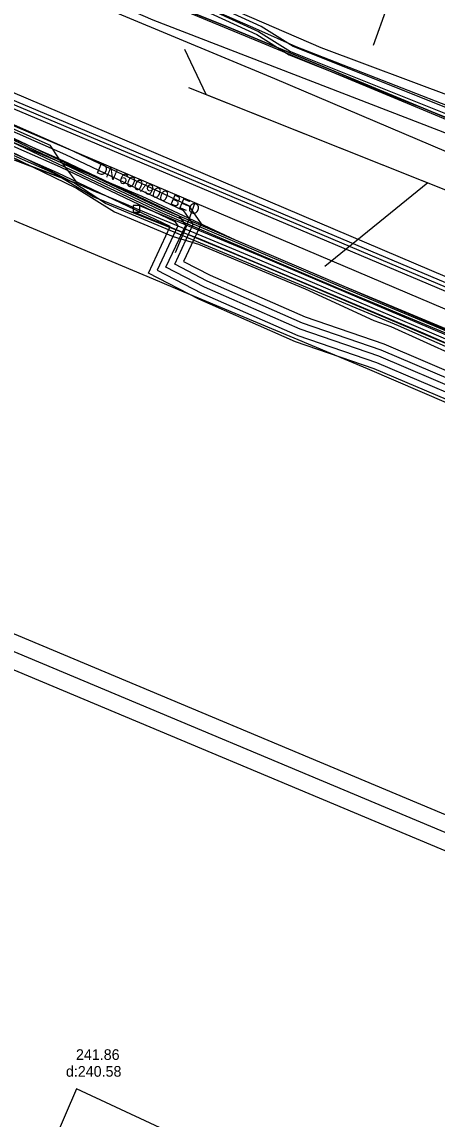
# Model space of a CAD drawing. Extents: x -596024 to -594475, y -1163820 to -1161957.
# Drawn here: x -594762.9 to -594731.8, y -1162272.9 to -1162190.6 of the extents above; entities that cross this region are included whole.
import ezdxf

# ---------------------------------------------------------------- set-up
doc = ezdxf.new("R2010")
doc.units = 0
for name, color, linetype in [('Level 1', 7, 'Continuous'), ('Vrstva 1', 7, 'Continuous'), ('Vrstva 10', 7, 'Continuous'), ('Vrstva 11', 7, 'Continuous'), ('Vrstva 12', 7, 'Continuous'), ('Vrstva 13', 7, 'Continuous'), ('Vrstva 19', 7, 'Continuous'), ('Vrstva 29', 7, 'Continuous'), ('Vrstva 30', 7, 'Continuous'), ('Vrstva 4', 7, 'Continuous'), ('Vrstva 42', 7, 'Continuous'), ('Vrstva 44', 7, 'Continuous'), ('Vrstva 55', 7, 'Continuous'), ('Vrstva 58', 7, 'Continuous'), ('Vrstva 9', 7, 'Continuous')]:
    doc.layers.add(name, color=color, linetype=linetype)

msp = doc.modelspace()

# ---------------------------------------------------------------- linework, layer by layer
at = {"layer": 'Level 1'}
for points in [[(-594749.13, -1162196.07), (-594750.72, -1162192.68)], [(-594750.45, -1162195.55), (-594709.77, -1162211.75), (-594681.66, -1162222.95), (-594639.16, -1162241.84), (-594604.2, -1162257.38), (-594561.16, -1162275.84)], [(-594732.5, -1162202.7), (-594740.23, -1162208.96)]]:
    msp.add_lwpolyline(points, dxfattribs=at)
at = {"layer": 'Vrstva 1'}
for p, q in [((-594758.849, -1162270.671), (-594770.885, -1162298.534)), ((-594744.151, -1162277.481), (-594758.849, -1162270.671))]:
    msp.add_line(p, q, dxfattribs=at)
msp.add_lwpolyline([(-594750.45, -1162195.55), (-594749.13, -1162196.07), (-594732.5, -1162202.7), (-594723.2, -1162206.4), (-594709.77, -1162211.75)], dxfattribs=at)
at = {"layer": 'Vrstva 10'}
for points in [[(-594776.154, -1162191.153), (-594772.298, -1162192.772), (-594764.852, -1162195.956), (-594763.349, -1162196.593), (-594741.779, -1162205.699), (-594725.074, -1162212.755), (-594718.123, -1162215.684)], [(-594718.357, -1162216.236), (-594725.307, -1162213.307), (-594742.013, -1162206.252), (-594763.583, -1162197.146), (-594765.087, -1162196.508), (-594772.532, -1162193.325), (-594776.386, -1162191.707)], [(-594708.531, -1162223.765), (-594716.132, -1162220.484), (-594733.443, -1162213.114), (-594744.984, -1162208.224), (-594754.234, -1162204.353)], [(-594708.769, -1162224.315), (-594716.368, -1162221.036), (-594733.677, -1162213.666), (-594745.216, -1162208.776), (-594754.466, -1162204.907)]]:
    msp.add_lwpolyline(points, dxfattribs=at)
at = {"layer": 'Vrstva 11'}
msp.add_lwpolyline([(-594754.6, -1162204.88), (-594754.1, -1162204.88), (-594754.1, -1162204.38), (-594754.6, -1162204.38)], close=True, dxfattribs=at)
msp.add_lwpolyline([(-594754.6, -1162204.88), (-594754.1, -1162204.88), (-594754.1, -1162204.38), (-594754.6, -1162204.38)], close=True, dxfattribs=at)
at = {"layer": 'Vrstva 12'}
msp.add_line((-594758.77, -1162202.76), (-594763.45, -1162200.98), dxfattribs=at)
for points in [[(-594691.9, -1162214.74), (-594693.41, -1162214.13), (-594708.66, -1162207.82), (-594726.57, -1162199.83), (-594745.03, -1162192.17), (-594754.89, -1162188.06), (-594753.69, -1162185.32)], [(-594797.84, -1162197.92), (-594795.26, -1162191.95), (-594785.4, -1162196.2), (-594782.44, -1162197.47), (-594767.54, -1162203.83), (-594753.11, -1162209.88)], [(-594767.38, -1162194.31), (-594722.65, -1162213.34), (-594687.5, -1162228.11)], [(-594767.74, -1162196.85), (-594765.07, -1162197.98), (-594760.82, -1162199.87)], [(-594766.88, -1162199.71), (-594758.77, -1162202.76)], [(-594758.77, -1162202.76), (-594758.93, -1162202.52), (-594760.19, -1162200.82), (-594760.82, -1162199.87)], [(-594669.22, -1162240.87), (-594677.04, -1162237.37), (-594688.06, -1162232.7), (-594698.57, -1162228.36), (-594704, -1162226.27), (-594707.98, -1162224.37), (-594708.65, -1162224.04), (-594716.25, -1162220.76), (-594733.56, -1162213.39), (-594745.1, -1162208.5), (-594754.35, -1162204.63), (-594755.28, -1162204.24), (-594755.87, -1162204), (-594756.43, -1162203.77), (-594756.78, -1162203.62), (-594757.22, -1162203.43), (-594757.54, -1162203.32), (-594758.33, -1162202.96), (-594758.77, -1162202.76), (-594758.93, -1162202.52), (-594760.19, -1162200.82), (-594760.82, -1162199.87)], [(-594758.33, -1162202.96), (-594758.77, -1162202.76)], [(-594758.33, -1162202.96), (-594758.77, -1162202.76)], [(-594757.54, -1162203.32), (-594758.33, -1162202.96)], [(-594757.54, -1162203.32), (-594758.33, -1162202.96)], [(-594757.22, -1162203.43), (-594757.54, -1162203.32)], [(-594757.22, -1162203.43), (-594757.54, -1162203.32)], [(-594756.78, -1162203.62), (-594757.22, -1162203.43)], [(-594756.78, -1162203.62), (-594757.22, -1162203.43)], [(-594756.43, -1162203.77), (-594756.78, -1162203.62)], [(-594756.43, -1162203.77), (-594756.78, -1162203.62)], [(-594755.87, -1162204), (-594756.43, -1162203.77)], [(-594755.87, -1162204), (-594756.43, -1162203.77)], [(-594755.28, -1162204.24), (-594755.87, -1162204)], [(-594755.28, -1162204.24), (-594755.87, -1162204)], [(-594754.35, -1162204.63), (-594755.28, -1162204.24)], [(-594753.11, -1162209.88), (-594750.79, -1162210.86)], [(-594750.79, -1162210.86), (-594737.05, -1162216.62), (-594699.17, -1162232.93)]]:
    msp.add_lwpolyline(points, dxfattribs=at)
at = {"layer": 'Vrstva 13'}
msp.add_lwpolyline([(-594836.23, -1162155.443), (-594836.196, -1162155.782), (-594816.247, -1162164.384), (-594814.935, -1162164.957), (-594803.879, -1162169.64), (-594755.473, -1162190.086), (-594744.01, -1162194.87), (-594731.121, -1162200.339), (-594730.015, -1162200.811), (-594704.47, -1162211.75), (-594699.45, -1162213.94), (-594673.314, -1162225.133)], dxfattribs=at)
at = {"layer": 'Vrstva 19'}
for points in [[(-594695.25, -1162276.17), (-594690.21, -1162265.28), (-594680.2, -1162243.33), (-594679.351, -1162240.241), (-594678.82, -1162238.33), (-594678.078, -1162235.421), (-594674.9, -1162222.97), (-594673.86, -1162218.9), (-594682.15, -1162216.27), (-594693.73, -1162211.66), (-594707.83, -1162205.54), (-594713.34, -1162203.16), (-594714.6, -1162202.61), (-594730.47, -1162196.31), (-594740.5, -1162192.55), (-594751.07, -1162187.95), (-594753.63, -1162189.06), (-594775.09, -1162179.85), (-594776.07, -1162176.84), (-594793.1, -1162168.81), (-594802.09, -1162164.76), (-594816.08, -1162158.49), (-594834.13, -1162150.42), (-594853.67, -1162141.96)], [(-594685.55, -1162231.56), (-594692.94, -1162228.45), (-594699.49, -1162225.65), (-594749.98, -1162204.19), (-594785.76, -1162188.98), (-594797.35, -1162184.05)], [(-594749.98, -1162204.19), (-594750.56, -1162205.79), (-594751.45, -1162207.94)]]:
    msp.add_lwpolyline(points, dxfattribs=at)
at = {"layer": 'Vrstva 29'}
msp.add_line((-594727.603, -1162252.954), (-594776.519, -1162232.441), dxfattribs=at)
at = {"layer": 'Vrstva 30'}
for p, q in [((-594776.036, -1162231.288), (-594727.903, -1162251.472)), ((-594727.302, -1162254.435), (-594777.002, -1162233.594))]:
    msp.add_line(p, q, dxfattribs=at)
at = {"layer": 'Vrstva 42'}
for points in [[(-594841.22, -1162164.89), (-594841.55, -1162165.818), (-594823.941, -1162173.342), (-594805.527, -1162181.255), (-594786.096, -1162189.732), (-594763.998, -1162199.133), (-594752.438, -1162204.617), (-594739.102, -1162210.309), (-594723.16, -1162216.972), (-594709.798, -1162222.556), (-594699.416, -1162226.808), (-594686.936, -1162232.243), (-594670.535, -1162239.442), (-594642.912, -1162251.21), (-594626.307, -1162258.207), (-594595.818, -1162271.123), (-594582.146, -1162276.922), (-594568.678, -1162282.65), (-594548.298, -1162291.531), (-594530.464, -1162298.451), (-594511.972, -1162306.232), (-594493.611, -1162313.902), (-594475.47, -1162321.871)], [(-594805, -1162180.3), (-594805.561, -1162181.567), (-594805.473, -1162181.605), (-594786.214, -1162190.008), (-594764.122, -1162199.407), (-594752.562, -1162204.891), (-594739.218, -1162210.585), (-594723.276, -1162217.248), (-594709.912, -1162222.834), (-594699.532, -1162227.084), (-594687.056, -1162232.517), (-594670.655, -1162239.718), (-594643.03, -1162251.486), (-594626.423, -1162258.483), (-594595.936, -1162271.399), (-594582.264, -1162277.198), (-594568.796, -1162282.926), (-594548.412, -1162291.809), (-594530.576, -1162298.729), (-594512.088, -1162306.508), (-594493.729, -1162314.178), (-594475.47, -1162322.199)], [(-594475.47, -1162322.035), (-594492.486, -1162314.56), (-594509.999, -1162307.221), (-594528.715, -1162299.349), (-594548.355, -1162291.67), (-594568.737, -1162282.788), (-594582.205, -1162277.06), (-594595.877, -1162271.261), (-594626.365, -1162258.345), (-594642.971, -1162251.348), (-594670.595, -1162239.58), (-594686.996, -1162232.38), (-594699.474, -1162226.946), (-594709.855, -1162222.695), (-594723.218, -1162217.11), (-594739.16, -1162210.447), (-594752.5, -1162204.754), (-594764.06, -1162199.27), (-594786.155, -1162189.87), (-594805.5, -1162181.43)], [(-594615.74, -1162262.79), (-594624.65, -1162259.07), (-594637.95, -1162253.48), (-594653.13, -1162246.96), (-594666.17, -1162241.28), (-594679.92, -1162235.52), (-594687.43, -1162232.45), (-594694.39, -1162229.4), (-594701, -1162226.48), (-594711.77, -1162221.9), (-594718.09, -1162219.27), (-594728.65, -1162214.76), (-594737.08, -1162211.18), (-594746.93, -1162206.99), (-594753.92, -1162203.71), (-594761.99, -1162200.35), (-594768.71, -1162197.49), (-594777.63, -1162193.65), (-594785.3, -1162190.25), (-594792.89, -1162187), (-594796.23, -1162185.84), (-594796.51, -1162185.77), (-594796.81, -1162185.85)], [(-594719.13, -1162220.27), (-594734.71, -1162213.43), (-594756.68, -1162204.25), (-594759.04, -1162202.69), (-594761.37, -1162201.52), (-594767.166, -1162198.707), (-594767.895, -1162200.415), (-594768.078, -1162200.336), (-594768.262, -1162200.258), (-594767.529, -1162198.541), (-594769.39, -1162198.13), (-594789.46, -1162189.22), (-594796.506, -1162186.659), (-594797.09, -1162187.201), (-594800.802, -1162195.021)], [(-594763.837, -1162200.659), (-594758.837, -1162203.099), (-594756.007, -1162204.859), (-594751.587, -1162206.709), (-594749.697, -1162207.299), (-594741.697, -1162210.639), (-594736.547, -1162213.009), (-594735.267, -1162213.479), (-594730.417, -1162215.679), (-594720.697, -1162219.769), (-594715.217, -1162222.125), (-594714.778, -1162222.42), (-594713.279, -1162223.092), (-594712.844, -1162222.824), (-594712.197, -1162221.469), (-594707.027, -1162209.629), (-594703.467, -1162201.819)]]:
    msp.add_lwpolyline(points, dxfattribs=at)
at = {"layer": 'Vrstva 44'}
msp.add_lwpolyline([(-594615.489, -1162264.329), (-594617.876, -1162263.185), (-594624.753, -1162260.392), (-594653.042, -1162248.004), (-594673.87, -1162239.439), (-594676.32, -1162238.996), (-594700.937, -1162228.271), (-594701.517, -1162227.634), (-594706.4, -1162225.55), (-594708.626, -1162224.544), (-594732.851, -1162213.96), (-594749.58, -1162206.904), (-594751.558, -1162206.159), (-594757.592, -1162203.739), (-594760.561, -1162201.965), (-594774.949, -1162195.637), (-594776.33, -1162195.028), (-594780.641, -1162193.061), (-594785.301, -1162190.858), (-594797.218, -1162185.869), (-594798.27, -1162185.406), (-594820.513, -1162176.019), (-594846.169, -1162165.001), (-594853.363, -1162161.962)], dxfattribs=at)
at = {"layer": 'Vrstva 55'}
for points in [[(-594752.53, -1162187.98), (-594745.42, -1162191.12), (-594742.39, -1162192.46), (-594730.47, -1162197.12)], [(-594729.61, -1162217.96), (-594735.99, -1162215.24), (-594741.89, -1162213.21), (-594749.04, -1162210.06), (-594751.48, -1162208.8), (-594750.09, -1162205.8), (-594750.8, -1162204.79), (-594759.66, -1162200.58), (-594768.61, -1162196.65)], [(-594767.62, -1162196.54), (-594759.45, -1162200.13), (-594750.46, -1162204.39), (-594749.51, -1162205.76), (-594750.82, -1162208.58), (-594748.82, -1162209.61), (-594741.71, -1162212.75), (-594735.81, -1162214.77), (-594729.42, -1162217.5)], [(-594729.84, -1162218.4), (-594736.17, -1162215.7), (-594742.08, -1162213.68), (-594749.25, -1162210.51), (-594752.14, -1162209.02), (-594750.66, -1162205.86), (-594751.13, -1162205.18), (-594759.86, -1162201.04), (-594768.44, -1162197.27)], [(-594768.26, -1162197.9), (-594760.07, -1162201.49), (-594751.47, -1162205.58), (-594751.24, -1162205.91), (-594752.79, -1162209.25), (-594749.47, -1162210.96), (-594742.26, -1162214.15), (-594736.35, -1162216.17), (-594730, -1162218.88)], [(-594671.35, -1162238.82), (-594675.31, -1162238.9), (-594677.31, -1162239.54), (-594677.53, -1162240.35), (-594678.35, -1162242.07), (-594679.96, -1162243.68), (-594683.01, -1162244.53), (-594696.54, -1162238.61), (-594696.59, -1162236.5), (-594698.58, -1162232.15), (-594700.76, -1162231.89), (-594709.45, -1162229.42), (-594721.25, -1162223.49), (-594722.48, -1162222.58), (-594724.08, -1162222.23), (-594730.27, -1162219.3), (-594736.53, -1162216.64), (-594742.43, -1162214.61), (-594749.68, -1162211.41), (-594753.45, -1162209.47), (-594751.82, -1162205.97), (-594760.28, -1162201.95), (-594768.08, -1162198.52)]]:
    msp.add_lwpolyline(points, dxfattribs=at)
at = {"layer": 'Vrstva 58'}
for points in [[(-594855.8, -1162145.62), (-594837.62, -1162153.37), (-594836.31, -1162153.98), (-594819.51, -1162161.12), (-594801.35, -1162168.87), (-594799.77, -1162169.48), (-594797.27, -1162170.37), (-594784.28, -1162175.73), (-594782.11, -1162176.71), (-594778.76, -1162179.27), (-594754.53, -1162189.16), (-594752.65, -1162189.31), (-594750.57, -1162189.75), (-594747.53, -1162190.99), (-594651.85, -1162230.77), (-594634.34, -1162238.31), (-594628.08, -1162237.31), (-594627.27, -1162237.69), (-594626.17, -1162238.17), (-594617.89, -1162242.16), (-594607.87, -1162246.62)], [(-594855.521, -1162146.975), (-594837.445, -1162154.525), (-594819.368, -1162162.393), (-594800.867, -1162170.155), (-594782.472, -1162177.705), (-594753.124, -1162190.465), (-594723.671, -1162201.842), (-594694.961, -1162212.9), (-594661.467, -1162226.404), (-594631.163, -1162239.589), (-594604.155, -1162251.18), (-594572.468, -1162264.684), (-594547.693, -1162277.762), (-594525.576, -1162287.119), (-594507.394, -1162294.988), (-594488.786, -1162302.856), (-594475.47, -1162308.493)], [(-594672.766, -1162221.374), (-594683.334, -1162216.877), (-594684.767, -1162216.516), (-594687.303, -1162216.516), (-594688.212, -1162216.173), (-594692.558, -1162214.57), (-594694.598, -1162214.201), (-594695.817, -1162214.059), (-594700.524, -1162211.418), (-594703.584, -1162210.146), (-594706.857, -1162208.909), (-594717.881, -1162203.895), (-594719.923, -1162202.648), (-594721.529, -1162201.453), (-594724.084, -1162200.028), (-594728.833, -1162198.03), (-594730.767, -1162197.189), (-594742.598, -1162192.46), (-594744.999, -1162190.966), (-594753.516, -1162187.044), (-594754.999, -1162186.388), (-594770.392, -1162180.507)], [(-594770.779, -1162181.097), (-594755.261, -1162187.025), (-594753.799, -1162187.672), (-594745.326, -1162191.574), (-594742.91, -1162193.078), (-594731.032, -1162197.825), (-594729.104, -1162198.664), (-594724.386, -1162200.649), (-594721.904, -1162202.033), (-594720.309, -1162203.22), (-594718.204, -1162204.505), (-594707.122, -1162209.545), (-594703.838, -1162210.787), (-594700.826, -1162212.039), (-594696.033, -1162214.727), (-594694.699, -1162214.883), (-594692.74, -1162215.237), (-594688.453, -1162216.819), (-594687.428, -1162217.205), (-594684.853, -1162217.205), (-594683.555, -1162217.532), (-594672.935, -1162222.05)], [(-594770.63, -1162180.87), (-594755.16, -1162186.78), (-594753.69, -1162187.43), (-594745.2, -1162191.34), (-594742.79, -1162192.84), (-594730.93, -1162197.58), (-594729, -1162198.42), (-594724.27, -1162200.41), (-594721.76, -1162201.81), (-594720.16, -1162203), (-594718.08, -1162204.27), (-594707.02, -1162209.3), (-594703.74, -1162210.54), (-594700.71, -1162211.8), (-594695.95, -1162214.47), (-594694.66, -1162214.62), (-594692.67, -1162214.98), (-594688.36, -1162216.57), (-594687.38, -1162216.94), (-594684.82, -1162216.94), (-594683.47, -1162217.28), (-594672.87, -1162221.79)], [(-594770.63, -1162180.87), (-594755.16, -1162186.78), (-594753.69, -1162187.43), (-594745.2, -1162191.34), (-594742.79, -1162192.84), (-594730.93, -1162197.58), (-594729, -1162198.42), (-594724.27, -1162200.41), (-594721.76, -1162201.81), (-594720.16, -1162203), (-594718.08, -1162204.27), (-594707.02, -1162209.3), (-594703.74, -1162210.54), (-594700.71, -1162211.8), (-594695.95, -1162214.47), (-594694.66, -1162214.62), (-594692.67, -1162214.98), (-594688.36, -1162216.57), (-594687.38, -1162216.94), (-594684.82, -1162216.94), (-594683.47, -1162217.28), (-594672.87, -1162221.79)], [(-594606.25, -1162247.31), (-594607.87, -1162246.62), (-594617.89, -1162242.16), (-594626.17, -1162238.17), (-594627.27, -1162237.69), (-594628.08, -1162237.31), (-594634.34, -1162238.31), (-594651.85, -1162230.77), (-594747.53, -1162190.99), (-594750.57, -1162189.75)]]:
    msp.add_lwpolyline(points, dxfattribs=at)
at = {"layer": 'Vrstva 9'}
msp.add_line((-594735.566, -1162189.546), (-594736.595, -1162192.378), dxfattribs=at)
msp.add_lwpolyline([(-594718.24, -1162215.96), (-594725.191, -1162213.031), (-594741.896, -1162205.976), (-594763.466, -1162196.87), (-594764.969, -1162196.232), (-594772.415, -1162193.048), (-594776.27, -1162191.43)], dxfattribs=at)

# ---------------------------------------------------------------- texts
at = {"layer": 'Vrstva 12'}
msp.add_text('DN 600/900 BEO', height=0.8, rotation=337.07107, dxfattribs=at).set_placement((-594757.422, -1162201.925))
at = {"layer": 'Vrstva 4'}
for s, p in [('241.86', (-594758.889, -1162268.491)), ('d:240.58', (-594759.642, -1162269.751))]:
    msp.add_text(s, height=0.8, dxfattribs=at).set_placement(p)

doc.saveas('drawing.dxf')
